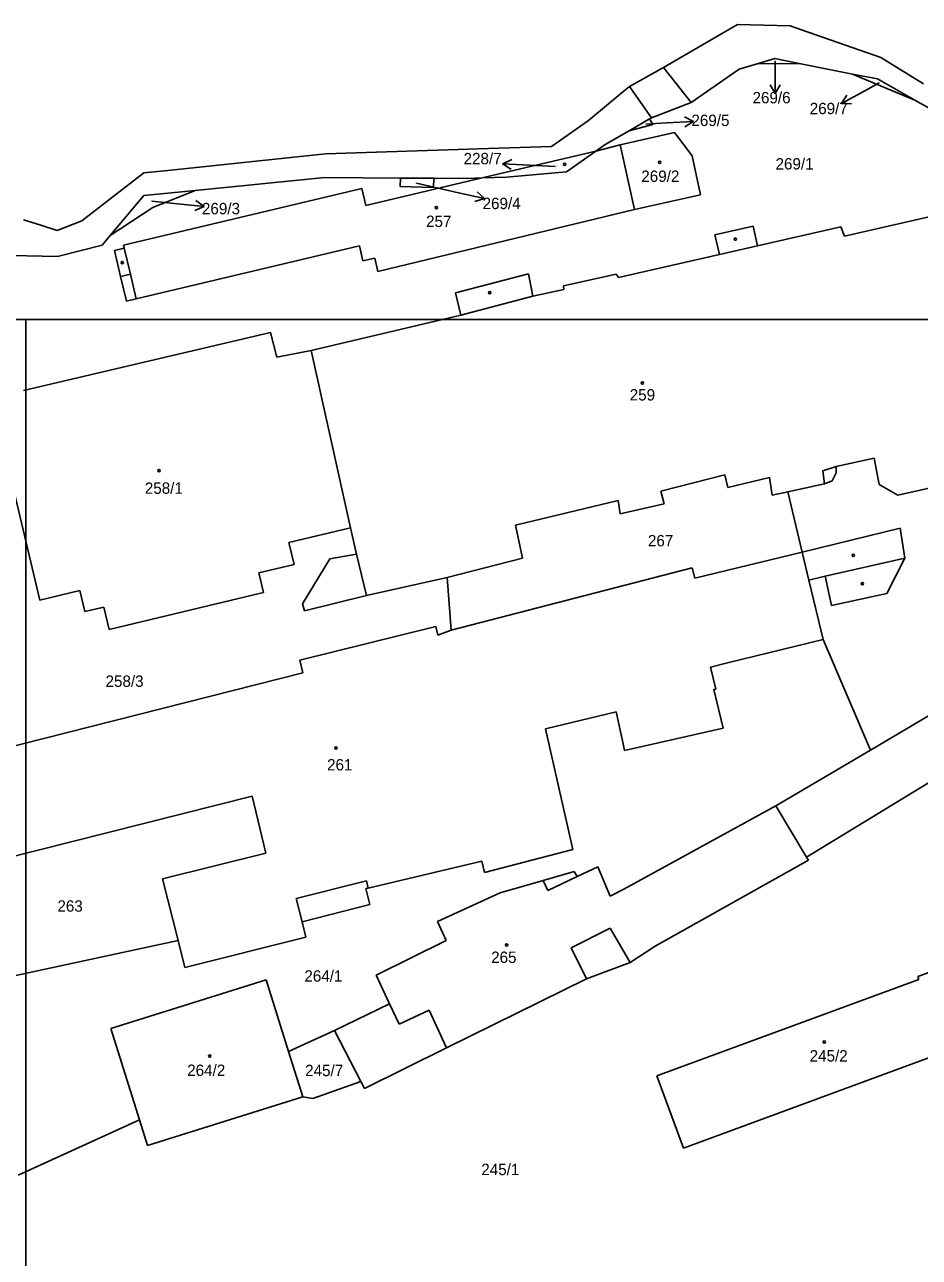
# Model space of a CAD drawing. Extents: x -670359 to -660124, y -978807 to -970072.
# Drawn here: x -669375.2 to -669241.5, y -977140.1 to -976955.9 of the extents above; entities that cross this region are included whole.
import ezdxf

# ---------------------------------------------------------------- set-up
doc = ezdxf.new("R2010")
doc.units = 0
for name, color, linetype in [('Hranice kat_území', 7, 'Continuous'), ('Hranice parcel', 7, 'Continuous'), ('ML1000', 7, 'Continuous'), ('Parcelní čísla', 7, 'Continuous'), ('Vnitřní kresba', 7, 'Continuous'), ('Značky budov', 7, 'Continuous'), ('Značky kultur', 7, 'Continuous')]:
    doc.layers.add(name, color=color, linetype=linetype)

msp = doc.modelspace()

# ---------------------------------------------------------------- linework, layer by layer
at = {"layer": 'Hranice kat_území'}
for p, q in [((-669260.77, -976956.11), (-669259.08, -976956.7)), ((-669259.08, -976956.7), (-669247.22, -976960.81)), ((-669290.92, -976970.25), (-669286.13, -976966.28)), ((-669286.13, -976966.28), (-669284.78, -976965.16)), ((-669330.22, -976975.25), (-669305.84, -976974.45)), ((-669305.84, -976974.45), (-669296.42, -976974.14))]:
    msp.add_line(p, q, dxfattribs=at)
for points in [[(-669279.68, -976962.33), (-669268.63, -976955.92)], [(-669268.63, -976955.92), (-669260.77, -976956.11)], [(-669247.22, -976960.81), (-669240.83, -976964.74)], [(-669284.78, -976965.16), (-669279.68, -976962.33)], [(-669296.42, -976974.14), (-669290.92, -976970.25)], [(-669353.79, -976977.72), (-669330.22, -976975.25)], [(-669365.09, -976984.06), (-669357.34, -976978.09)], [(-669357.34, -976978.09), (-669353.79, -976977.72)], [(-669366.61, -976985.24), (-669365.09, -976984.06)], [(-669375.35, -976985.08), (-669372.93, -976985.84)], [(-669372.93, -976985.84), (-669370.32, -976986.66)], [(-669370.32, -976986.66), (-669366.61, -976985.24)]]:
    msp.add_lwpolyline(points, dxfattribs=at)
at = {"layer": 'Hranice parcel'}
for points in [[(-669265.7, -976961.77), (-669263.07, -976961)], [(-669263.07, -976961), (-669259.45, -976961.72)], [(-669275.56, -976967.54), (-669268.38, -976962.56)], [(-669268.38, -976962.56), (-669265.7, -976961.77)], [(-669265.7, -976961.77), (-669259.45, -976961.72)], [(-669259.45, -976961.72), (-669251.45, -976963.3)], [(-669251.45, -976963.3), (-669242.12, -976967.2)], [(-669251.45, -976963.3), (-669247.74, -976964.03)], [(-669247.74, -976964.03), (-669242.12, -976967.2)], [(-669281.49, -976969.84), (-669275.56, -976967.54)], [(-669242.12, -976967.2), (-669238.42, -976969.29)], [(-669284.85, -976971.77), (-669281.3, -976970.86), (-669281.8, -976970.02)], [(-669281.8, -976970.02), (-669284.85, -976971.77)], [(-669281.49, -976969.84), (-669281.8, -976970.02)], [(-669284.85, -976971.77), (-669288.41, -976973.81)], [(-669286.19, -976973.86), (-669278.06, -976972.05)], [(-669278.06, -976972.05), (-669275.44, -976975.55)], [(-669289.84, -976974.81), (-669288.41, -976973.81)], [(-669286.19, -976973.86), (-669289.84, -976974.81)], [(-669284.03, -976983.55), (-669286.19, -976973.86)], [(-669289.84, -976974.81), (-669306.79, -976978.83)], [(-669294.21, -976977.9), (-669289.84, -976974.81)], [(-669275.44, -976975.55), (-669274.15, -976981.35)], [(-669349.69, -976980.7), (-669330.33, -976978.77)], [(-669330.33, -976978.77), (-669319, -976978.84)], [(-669306.79, -976978.83), (-669324.21, -976982.96)], [(-669319, -976978.84), (-669319.06, -976980.1), (-669314.11, -976980.25), (-669314, -976978.88)], [(-669319, -976978.84), (-669314, -976978.88)], [(-669314, -976978.88), (-669309.07, -976978.91)], [(-669306.79, -976978.83), (-669309.07, -976978.91)], [(-669306.79, -976978.83), (-669303.17, -976978.71)], [(-669303.17, -976978.71), (-669294.21, -976977.9)], [(-669362.38, -976987.44), (-669356.01, -976983.23), (-669349.69, -976980.7)], [(-669324.81, -976980.41), (-669360.4, -976988.86)], [(-669357.38, -976981.46), (-669349.69, -976980.7)], [(-669324.21, -976982.96), (-669324.81, -976980.41)], [(-669274.15, -976981.35), (-669284.03, -976983.55)], [(-669362.38, -976987.44), (-669357.38, -976981.46)], [(-669322.38, -976992.83), (-669284.03, -976983.55)], [(-669236.95, -976983.94), (-669252.64, -976987.51)], [(-669266.32, -976986.02), (-669272.03, -976987.32)], [(-669265.65, -976988.99), (-669266.32, -976986.02)], [(-669253.21, -976986.16), (-669265.65, -976988.99)], [(-669252.64, -976987.51), (-669253.21, -976986.16)], [(-669363.59, -976988.89), (-669362.38, -976987.44)], [(-669272.03, -976987.32), (-669271.35, -976990.28)], [(-669377.15, -976990.43), (-669370.26, -976990.58)], [(-669370.26, -976990.58), (-669363.59, -976988.89)], [(-669360.29, -976989.34), (-669361.75, -976989.68)], [(-669361.75, -976989.68), (-669360.83, -976993.54)], [(-669360.4, -976988.86), (-669360.29, -976989.34)], [(-669358.49, -976996.91), (-669325.14, -976989)], [(-669325.14, -976989), (-669324.62, -976991.22)], [(-669271.35, -976990.28), (-669286.43, -976993.71)], [(-669324.62, -976991.22), (-669322.86, -976990.8)], [(-669322.86, -976990.8), (-669322.38, -976992.83)], [(-669360.83, -976993.54), (-669359.95, -976997.26)], [(-669299.87, -976993.15), (-669310.81, -976996.01)], [(-669299.21, -976996.5), (-669299.87, -976993.15)], [(-669286.76, -976993.23), (-669294.66, -976994.96)], [(-669286.43, -976993.71), (-669286.76, -976993.23)], [(-669310.81, -976996.01), (-669309.99, -976999.36)], [(-669294.58, -976995.52), (-669299.21, -976996.5)], [(-669294.66, -976994.96), (-669294.58, -976995.52)], [(-669359.95, -976997.26), (-669358.49, -976996.91)], [(-669309.99, -976999.36), (-669332.36, -977004.61)], [(-669375.35, -977010.62), (-669338.45, -977001.93)], [(-669338.45, -977001.93), (-669337.47, -977005.6)], [(-669337.47, -977005.6), (-669332.36, -977004.61)], [(-669332.36, -977004.61), (-669326.48, -977031.13)], [(-669372.89, -977041.92), (-669378.87, -977016.91)], [(-669248.22, -977020.73), (-669253.89, -977021.96)], [(-669247.48, -977024.64), (-669248.22, -977020.73)], [(-669270.52, -977023.18), (-669280.1, -977025.64)], [(-669270.11, -977025.1), (-669270.52, -977023.18)], [(-669263.88, -977023.62), (-669270.11, -977025.1)], [(-669263.47, -977026.26), (-669263.88, -977023.62)], [(-669253.89, -977022.92), (-669254.52, -977024.12)], [(-669253.89, -977021.96), (-669253.89, -977022.92)], [(-669255.64, -977024.53), (-669261.13, -977025.74)], [(-669254.52, -977024.12), (-669255.64, -977024.53)], [(-669244.67, -977026.22), (-669247.48, -977024.64)], [(-669234.69, -977024.01), (-669244.67, -977026.22)], [(-669286.49, -977027.03), (-669301.83, -977030.72)], [(-669286.16, -977029.03), (-669286.49, -977027.03)], [(-669280.1, -977025.64), (-669279.61, -977027.55)], [(-669261.13, -977025.74), (-669263.47, -977026.26)], [(-669258.97, -977034.74), (-669261.13, -977025.74)], [(-669279.61, -977027.55), (-669286.16, -977029.03)], [(-669301.83, -977030.72), (-669300.76, -977035.67)], [(-669326.48, -977031.13), (-669335.68, -977033.33)], [(-669325.6, -977035.06), (-669326.48, -977031.13)], [(-669258.97, -977034.74), (-669244.33, -977031.18)], [(-669244.33, -977031.18), (-669243.66, -977035.65)], [(-669335.68, -977033.33), (-669334.9, -977036.58)], [(-669275, -977038.63), (-669258.97, -977034.74)], [(-669334.9, -977036.58), (-669340.19, -977037.85)], [(-669325.6, -977035.06), (-669324.08, -977041.24)], [(-669300.76, -977035.67), (-669312.02, -977038.53)], [(-669243.66, -977035.65), (-669246.35, -977040.94)], [(-669340.19, -977037.85), (-669339.48, -977040.8)], [(-669311.42, -977046.44), (-669275.4, -977037.12)], [(-669275.4, -977037.12), (-669275, -977038.63)], [(-669255.56, -977038.36), (-669257.96, -977038.93)], [(-669254.58, -977042.74), (-669255.56, -977038.36)], [(-669324.08, -977041.24), (-669312.02, -977038.53)], [(-669312.02, -977038.53), (-669311.42, -977046.44)], [(-669257.96, -977038.93), (-669255.83, -977047.79)], [(-669366.93, -977040.49), (-669372.89, -977041.92)], [(-669366.18, -977043.64), (-669366.93, -977040.49)], [(-669339.48, -977040.8), (-669362.57, -977046.32)], [(-669246.35, -977040.94), (-669254.58, -977042.74)], [(-669363.36, -977042.97), (-669366.18, -977043.64)], [(-669362.57, -977046.32), (-669363.36, -977042.97)], [(-669334.03, -977050.89), (-669313.74, -977045.89)], [(-669313.74, -977045.89), (-669313.42, -977047.17)], [(-669313.42, -977047.17), (-669311.42, -977046.44)], [(-669270.13, -977051.31), (-669255.83, -977047.79)], [(-669255.83, -977047.79), (-669248.79, -977064.37)], [(-669333.62, -977052.81), (-669334.03, -977050.89)], [(-669285.74, -977063.39), (-669285.52, -977064.39), (-669270.81, -977061.04), (-669272.19, -977055.29), (-669271.86, -977055.22), (-669272.66, -977051.93), (-669270.13, -977051.31)], [(-669411.24, -977072.45), (-669333.62, -977052.81)], [(-669231.17, -977053.95), (-669248.79, -977064.37)], [(-669297.35, -977061.14), (-669286.8, -977058.6)], [(-669286.8, -977058.6), (-669285.74, -977063.39)], [(-669293.25, -977079.18), (-669297.35, -977061.14)], [(-669248.79, -977064.37), (-669262.9, -977072.68)], [(-669258.34, -977080.32), (-669232.56, -977064.67)], [(-669389.6, -977083.42), (-669341.17, -977071.24)], [(-669341.17, -977071.24), (-669339.11, -977079.72)], [(-669285.62, -977085.12), (-669262.9, -977072.68)], [(-669262.9, -977072.68), (-669258.34, -977080.32)], [(-669339.11, -977079.72), (-669354.57, -977083.58)], [(-669306.43, -977082.61), (-669293.25, -977079.18)], [(-669258.05, -977080.8), (-669280.94, -977093.65)], [(-669258.05, -977080.8), (-669258.34, -977080.32)], [(-669306.84, -977080.94), (-669323.84, -977084.96)], [(-669306.84, -977080.94), (-669306.43, -977082.61)], [(-669293.06, -977082.5), (-669297.68, -977083.82)], [(-669292.58, -977083.24), (-669293.06, -977082.5)], [(-669289.54, -977081.81), (-669292.58, -977083.24)], [(-669287.68, -977086.19), (-669289.54, -977081.81)], [(-669354.57, -977083.58), (-669352.25, -977092.79)], [(-669297.68, -977083.82), (-669304.09, -977085.66)], [(-669324.17, -977085.03), (-669323.84, -977084.96)], [(-669323.59, -977087.43), (-669324.17, -977085.03)], [(-669304.09, -977085.66), (-669313.47, -977089.94)], [(-669285.62, -977085.12), (-669287.68, -977086.19)], [(-669323.59, -977087.43), (-669333.71, -977090.02)], [(-669333.14, -977092.29), (-669333.71, -977090.02)], [(-669313.47, -977089.94), (-669312.18, -977092.81)], [(-669376.48, -977098.05), (-669352.25, -977092.79)], [(-669351.24, -977096.82), (-669352.25, -977092.79)], [(-669351.24, -977096.82), (-669333.14, -977092.29)], [(-669312.18, -977092.81), (-669322.62, -977097.99)], [(-669280.94, -977093.65), (-669284.68, -977096.07)], [(-669284.68, -977096.07), (-669291.23, -977098.5)], [(-669235.38, -977095.86), (-669241.7, -977098.19)], [(-669339.07, -977098.69), (-669362.29, -977105.94)], [(-669335.73, -977109.4), (-669339.07, -977098.69)], [(-669322.62, -977097.99), (-669320.63, -977102.24)], [(-669291.23, -977098.5), (-669312.15, -977108.86)], [(-669241.55, -977098.61), (-669280.68, -977113.03)], [(-669241.7, -977098.19), (-669241.55, -977098.61)], [(-669328.85, -977106.24), (-669320.63, -977102.24)], [(-669362.29, -977105.94), (-669358.02, -977119.6)], [(-669328.85, -977106.24), (-669335.73, -977109.4)], [(-669328.85, -977106.24), (-669324.93, -977113.89)], [(-669333.62, -977116.15), (-669335.73, -977109.4)], [(-669312.15, -977108.86), (-669324.41, -977114.92)], [(-669276.7, -977123.85), (-669237.53, -977109.41)], [(-669332.12, -977116.43), (-669324.93, -977113.89)], [(-669324.41, -977114.92), (-669324.93, -977113.89)], [(-669280.68, -977113.03), (-669276.7, -977123.85)], [(-669356.83, -977123.41), (-669333.62, -977116.15)], [(-669333.62, -977116.15), (-669332.12, -977116.43)], [(-669376.16, -977127.86), (-669358.02, -977119.6)], [(-669358.02, -977119.6), (-669356.83, -977123.41)]]:
    msp.add_lwpolyline(points, dxfattribs=at)
at = {"layer": 'ML1000'}
for points in [[(-669375, -977000), (-669375, -977500), (-670000, -977500), (-670000, -977000)], [(-668750, -977000), (-668750, -977500), (-669375, -977500), (-669375, -977000)]]:
    msp.add_lwpolyline(points, close=True, dxfattribs=at)
at = {"layer": 'Parcelní čísla'}
for p, q in [((-669263.01, -976961.42), (-669263.01, -976962.23)), ((-669247.47, -976964.62), (-669249.59, -976965.79)), ((-669262.26, -976964.93), (-669263.01, -976966.23)), ((-669251.59, -976967.75), (-669253.09, -976967.72)), ((-669276.57, -976969.71), (-669275.24, -976970.38)), ((-669282.35, -976970.77), (-669279.23, -976970.6)), ((-669302.45, -976977.55), (-669303.72, -976976.74)), ((-669295.91, -976977.11), (-669299.72, -976976.93)), ((-669316.61, -976979.63), (-669310.35, -976981.04)), ((-669307.55, -976980.9), (-669306.45, -976981.92)), ((-669356.15, -976982.31), (-669352.35, -976982.69)), ((-669349.59, -976982.21), (-669348.37, -976983.09))]:
    msp.add_line(p, q, dxfattribs=at)
for points in [[(-669263.01, -976962.23), (-669263.01, -976966.23), (-669263.76, -976964.93)], [(-669249.59, -976965.79), (-669253.09, -976967.72), (-669252.32, -976966.44)], [(-669279.23, -976970.6), (-669275.24, -976970.38), (-669276.49, -976971.2)], [(-669299.72, -976976.93), (-669303.72, -976976.74), (-669302.38, -976976.05)], [(-669310.35, -976981.04), (-669306.45, -976981.92), (-669307.88, -976982.36)], [(-669352.35, -976982.69), (-669348.37, -976983.09), (-669349.74, -976983.71)]]:
    msp.add_lwpolyline(points, dxfattribs=at)
at = {"layer": 'Vnitřní kresba'}
for points in [[(-669275.56, -976967.54), (-669279.68, -976962.33)], [(-669284.78, -976965.16), (-669281.49, -976969.84)], [(-669360.29, -976989.34), (-669359.37, -976993.2)], [(-669271.35, -976990.28), (-669265.65, -976988.99)], [(-669360.83, -976993.54), (-669359.37, -976993.2)], [(-669359.37, -976993.2), (-669358.49, -976996.91)], [(-669309.99, -976999.36), (-669299.21, -976996.5)], [(-669255.89, -977022.61), (-669253.89, -977021.96)], [(-669255.64, -977024.53), (-669255.89, -977022.61)], [(-669258.97, -977034.74), (-669257.96, -977038.93)], [(-669329.55, -977035.76), (-669333.67, -977042.5)], [(-669325.6, -977035.06), (-669329.55, -977035.76)], [(-669255.56, -977038.36), (-669243.66, -977035.65)], [(-669333.35, -977043.53), (-669324.08, -977041.24)], [(-669333.67, -977042.5), (-669333.35, -977043.53)], [(-669334.59, -977086.51), (-669324.11, -977083.88)], [(-669324.11, -977083.88), (-669323.84, -977084.96)], [(-669297.68, -977083.82), (-669296.97, -977085.32)], [(-669296.97, -977085.32), (-669292.58, -977083.24)], [(-669333.71, -977090.02), (-669334.59, -977086.51)], [(-669293.49, -977093.88), (-669287.67, -977090.97)], [(-669287.67, -977090.97), (-669284.68, -977096.07)], [(-669291.23, -977098.5), (-669293.49, -977093.88)], [(-669320.63, -977102.24), (-669319.19, -977105.3)], [(-669319.19, -977105.3), (-669314.71, -977103.22)], [(-669314.71, -977103.22), (-669312.15, -977108.86)]]:
    msp.add_lwpolyline(points, dxfattribs=at)
at = {"layer": 'Značky budov'}
for centre in [(-669280.28, -976976.5), (-669313.64, -976983.25), (-669282.86, -977009.49), (-669355.09, -977022.57), (-669328.65, -977064.05), (-669303.16, -977093.49), (-669255.67, -977107.96), (-669347.51, -977110.06)]:
    msp.add_circle(centre, 0.175, dxfattribs=at)
at = {"layer": 'Značky kultur'}
for centre in [(-669294.48, -976976.79), (-669280.28, -976976.5), (-669313.64, -976983.25), (-669268.95, -976987.98), (-669360.6, -976991.47), (-669305.66, -976995.98), (-669282.86, -977009.49), (-669355.09, -977022.57), (-669251.35, -977035.25), (-669249.98, -977039.49), (-669328.65, -977064.05), (-669303.16, -977093.49), (-669255.67, -977107.96), (-669347.51, -977110.06)]:
    msp.add_circle(centre, 0.175, dxfattribs=at)

# ---------------------------------------------------------------- texts
at = {"layer": 'Parcelní čísla'}
for s, height, p in [('269/6', 0.1, (-669263.21, -976961.42)), ('269/7', 0.1, (-669247.67, -976964.62)), ('269/6', 1.7, (-669266.4, -976967.68)), ('269/7', 1.7, (-669257.85, -976969.3)), ('269/5', 1.7, (-669275.53, -976971.07)), ('269/5', 0.1, (-669282.55, -976970.77)), ('228/7', 1.7, (-669309.58, -976976.79)), ('269/1', 1.7, (-669262.96, -976977.57)), ('228/7', 0.1, (-669295.91, -976977.11)), ('269/2', 1.7, (-669283.02, -976979.42)), ('269/4', 0.1, (-669316.81, -976979.63)), ('269/3', 0.1, (-669356.35, -976982.31)), ('269/3', 1.7, (-669348.68, -976984.26)), ('269/4', 1.7, (-669306.74, -976983.49)), ('257', 1.7, (-669315.19, -976986.16)), ('259', 1.7, (-669284.75, -977012.09)), ('258/1', 1.7, (-669357.22, -977026.04)), ('267', 1.7, (-669282.03, -977033.89)), ('258/3', 1.7, (-669363.09, -977054.89)), ('261', 1.7, (-669329.98, -977067.38)), ('263', 1.7, (-669370.28, -977088.49)), ('265', 1.7, (-669305.46, -977096.15)), ('264/1', 1.7, (-669333.37, -977098.95)), ('245/2', 1.7, (-669257.86, -977110.88)), ('264/2', 1.7, (-669350.89, -977113.04)), ('245/7', 1.7, (-669333.26, -977113.07)), ('245/1', 1.7, (-669306.93, -977127.86))]:
    msp.add_text(s, height=height, dxfattribs=at).set_placement(p)

doc.saveas('drawing.dxf')
